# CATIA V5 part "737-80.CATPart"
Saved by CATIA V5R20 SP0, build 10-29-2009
Part number: 737-80
Definition: NONE
Nomenclature: 737-80
Source: Unknown
Description: 737-80
Bounding box of the stored display mesh (mm): x -74 to 56, y -74 to 74, z -75 to 50
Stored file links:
  C:\Users\Utente\Desktop\IO LAVORO\3D X SITO CF\X SITO\737\737-80.CATPart
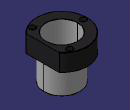
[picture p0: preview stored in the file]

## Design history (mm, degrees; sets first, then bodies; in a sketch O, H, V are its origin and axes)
Body1 "737-80" (main body)
  Solid1: solid without history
